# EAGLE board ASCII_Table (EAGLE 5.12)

No outline drawn. Coordinates in mm, seen from the top.
Copper layers (1*16): Top 0.035mm / dielectric 1.5mm / Bottom 0.035mm
Design rules "default": minimum track width 10mil, minimum drill 0.6mm, track to track 8mil, track to pad 8mil, pad to pad 8mil, via to via 8mil, smd to smd 8mil, copper to edge 40mil, drill to drill 8mil, minimum pad ring 10mil, minimum via ring 8mil, stop-mask expansion 4mil, vias tented up to drill 0mil, thermal gap 10mil

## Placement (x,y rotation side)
E$1  [LAYER_10-1-140321-213148]  200,40 0 top
E$2  [LAYER_10-1-140321-213244]  200,50 0 top
E$3  [LAYER_10-1-140321-213318]  200,60 0 top
E$4  [LAYER_10-1-140321-213342]  200,70 0 top
E$5  [HEY__ITA-1-140321-213614]  200,100 0 top
E$6  [WIDTH_FA-1-140321-213720]  200,110 0 top
E$7  [WIDTH_FA-1-140321-213743]  200,130 0 top
E$8  [WIDTH_FA-1-140321-213808]  200,120 0 top
E$9  [NEGATIVE-1-140321-214252]  200,90 0 top
E$10  [SPECIAL_-1-140321-214501]  200,80 0 top

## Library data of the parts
E$1-E$10 = ASCII_Table

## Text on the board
Document: Layer 48
100_Table_grid: 0x00 | 0x01 | 0x02 | 0x03 | 0x04 | 0x05 | 0x06 | 0x07 | 0x08 | 0x09 | 0x0A | 0x0B | 0x0C | 0x0D | 0x0E | 0x0F | 0 | 1 | 2 | 3 | 4 | 5 | 6 | 7 | 8 | 9 | 10 | 11 | 12 | 13 | 14 | 15 | Slope, wire width and width factor | 0x20 | 32 | 0x30 | 48 | 0x40 | 64 | 0x50 | 80 | 0x60 | 96 | 0x70 | 112 | 0x80 | 128 | 0x90 | 144 | 0xA0 | 160 | 0xB0 | 176 | 0xC0 | 192 | 0xD0 | 208 | 0xE0 | 224 | 0xF0 | 240 | ASCII Table of Hershey Text for EAGLE | Display Layers 101 through 108 to view the fonts. Library has text stored on Layer 48 Document
101_ASCII_Code: 32 | 33 | 34 | 35 | 36 | 37 | 38 | 39 | 40 | 41 | 42 | 43 | 44 | 45 | 46 | 47 | 48 | 49 | 50 | 51 | 52 | 53 | 54 | 55 | 56 | 57 | 58 | 59 | 60 | 61 | 62 | 63 | 64 | 65 | 66 | 67 | 68 | 69 | 70 | 71 | 72 | 73 | 74 | 75 | 76 | 77 | 78 | 79 | 80 | 81 | 82 | 83 | 84 | 85 | 86 | 87 | 88 | 89 | 90 | 91 | 92 | 93 | 94 | 95 | 96 | 97 | 98 | 99 | 100 | 101 | 102 | 103 | 104 | 105 | 106 | 107 | 108 | 109 | 110 | 111 | 112 | 113 | 114 | 115 | 116 | 117 | 118 | 119 | 120 | 121 | 122 | 123 | 124 | 125 | 126 | 127 | 128 | 129 | 130 | 131 | 132 | 133 | 134 | 135 | 136 | 137 | 138 | 139 | 140 | 141 | 142 | 143 | 144 | 145 | 146 | 147 | 148 | 149 | 150 | 151 | 152 | 153 | 154 | 155 | 156 | 157 | 158 | 159 | 160 | 161 | 162 | 163 | 164 | 165 | 166 | 167 | 168 | 169 | 170 | 171 | 172 | 173 | 174 | 175 | 176 | 177 | 178 | 179 | 180 | 181 | 182 | 183 | 184 | 185 | 186 | 187 | 188 | 189 | 190 | 191 | 192 | 193 | 194 | 195 | 196 | 197 | 198 | 199 | 200 | 201 | 202 | 203 | 204 | 205 | 206 | 207 | 208 | 209 | 210 | 211 | 212 | 213 | 214 | 215 | 216 | 217 | 218 | 219 | 220 | 221 | 222 | 223 | 224 | 225 | 226 | 227 | 228 | 229 | 230 | 231 | 232 | 233 | 234 | 235 | 236 | 237 | 238 | 239 | LAYER 101 101_ASCII_Code | 240 | 241 | 242 | 243 | 244 | 245 | 246 | 247 | 248 | 249 | 250 | 251 | 252 | 253 | 254 | 255
102_PROPORTIONAL: ! | " | # | $ | % | & | ' | ( | ) | * | + | , | - | . | / | 0 | 1 | 2 | 3 | 4 | 5 | 6 | 7 | 8 | 9 | : | ; | < | = | > | ? | @ | A | B | C | D | E | F | G | H | I | J | K | L | M | N | O | P | Q | R | S | T | U | V | W | X | Y | Z | [ | \ | ] | ^ | _ | ` | a | b | c | d | e | f | g | h | i | j | k | l | m | n | o | p | q | r | s | t | u | v | w | x | y | z | { | | | } | ~ |  |  |  |  |  |  |  |  |  |  |  |  |  |  |  |  |  |  |  |  |  |  |  |  |  |  |  |  |  |  |  |  | ¡ | ¢ | £ | ¤ | ¥ | ¦ | § | ¨ | © | ª | « | ¬ | ­ | ® | ¯ | ° | ± | ² | ³ | ´ | µ | ¶ | · | ¸ | ¹ | º | » | ¼ | ½ | ¾ | ¿ | À | Á | Â | Ã | Ä | Å | Æ | Ç | È | É | Ê | Ë | Ì | Í | Î | Ï | Ð | Ñ | Ò | Ó | Ô | Õ | Ö | × | Ø | Ù | Ú | Û | Ü | Ý | Þ | ß | à | á | â | ã | ä | å | æ | ç | è | é | ê | ë | ì | í | î | ï | LAYER 102 102_PROPORTIONAL | ð | ñ | ò | ó | ô | õ | ö | ÷ | ø | ù | ú | û | ü | ý | þ | ÿ
103_FIXED: ! | " | # | $ | % | & | ' | ( | ) | * | + | , | - | . | / | 0 | 1 | 2 | 3 | 4 | 5 | 6 | 7 | 8 | 9 | : | ; | < | = | > | ? | @ | A | B | C | D | E | F | G | H | I | J | K | L | M | N | O | P | Q | R | S | T | U | V | W | X | Y | Z | [ | \ | ] | ^ | _ | ` | a | b | c | d | e | f | g | h | i | j | k | l | m | n | o | p | q | r | s | t | u | v | w | x | y | z | { | | | } | ~ |  |  |  |  |  |  |  |  |  |  |  |  |  |  |  |  |  |  |  |  |  |  |  |  |  |  |  |  |  |  |  |  | ¡ | ¢ | £ | ¤ | ¥ | ¦ | § | ¨ | © | ª | « | ¬ | ­ | ® | ¯ | ° | ± | ² | ³ | ´ | µ | ¶ | · | ¸ | ¹ | º | » | ¼ | ½ | ¾ | ¿ | À | Á | Â | Ã | Ä | Å | Æ | Ç | È | É | Ê | Ë | Ì | Í | Î | Ï | Ð | Ñ | Ò | Ó | Ô | Õ | Ö | × | Ø | Ù | Ú | Û | Ü | Ý | Þ | ß | LAYER 103 103_FIXED | à | á | â | ã | ä | å | æ | ç | è | é | ê | ë | ì | í | î | ï | ð | ñ | ò | ó | ô | õ | ö | ÷ | ø | ù | ú | û | ü | ý | þ | ÿ
104_VECTOR: ! | " | # | $ | % | & | ' | ( | ) | * | + | , | - | . | / | 0 | 1 | 2 | 3 | 4 | 5 | 6 | 7 | 8 | 9 | : | ; | < | = | > | ? | @ | A | B | C | D | E | F | G | H | I | J | K | L | M | N | O | P | Q | R | S | T | U | V | W | X | Y | Z | [ | \ | ] | ^ | _ | ` | a | b | c | d | e | f | g | h | i | j | k | l | m | n | o | p | q | r | s | t | u | v | w | x | y | z | { | | | } | ~ |  |  |  |  |  |  |  |  |  |  |  |  |  |  |  |  |  |  |  |  |  |  |  |  |  |  |  |  |  |  |  |  | ¡ | ¢ | £ | ¤ | ¥ | ¦ | § | ¨ | © | ª | « | ¬ | ­ | ® | ¯ | ° | ± | ² | ³ | ´ | µ | ¶ | · | ¸ | ¹ | º | » | ¼ | ½ | ¾ | ¿ | À | Á | Â | Ã | Ä | Å | Æ | Ç | È | É | Ê | Ë | Ì | Í | Î | Ï | LAYER 104 104_VECTOR | Ð | Ñ | Ò | Ó | Ô | Õ | Ö | × | Ø | Ù | Ú | Û | Ü | Ý | Þ | ß | à | á | â | ã | ä | å | æ | ç | è | é | ê | ë | ì | í | î | ï | ð | ñ | ò | ó | ô | õ | ö | ÷ | ø | ù | ú | û | ü | ý | þ | ÿ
